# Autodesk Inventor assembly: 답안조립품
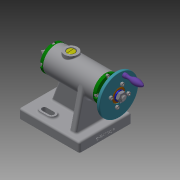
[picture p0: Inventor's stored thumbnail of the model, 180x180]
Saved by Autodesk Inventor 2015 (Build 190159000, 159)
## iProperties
Created: 2022-06
Part Number: 답안조립품
Document SubType Name: Assembly
Designer: 1048888
Author: 1048888
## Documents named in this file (18)
- C:\Users\1048888\Desktop\720606V1012\답안조립품.iam
- C:\Users\1048888\Desktop\720606V1012\나사.ipt
- C:\Users\1048888\Desktop\720606V1012\나사축.ipt
- C:\Users\1048888\Desktop\720606V1012\너트 M8.ipt
- C:\Users\1048888\Desktop\720606V1012\돌림판.ipt
- C:\Users\1048888\Desktop\720606V1012\멈춤나사 M3.ipt
- C:\Users\1048888\Desktop\720606V1012\본체.ipt
- C:\Users\1048888\Desktop\720606V1012\볼트 M3.ipt
- C:\Users\1048888\Desktop\720606V1012\부시.ipt
- C:\Users\1048888\Desktop\720606V1012\센터.ipt
- C:\Users\1048888\Desktop\720606V1012\센터홀더.ipt
- C:\Users\1048888\Desktop\720606V1012\슬리브.ipt
- C:\Users\1048888\Desktop\720606V1012\와셔.ipt
- C:\Users\1048888\Desktop\720606V1012\중공축.ipt
- C:\Users\1048888\Desktop\720606V1012\커버.ipt
- C:\Users\1048888\Desktop\720606V1012\키 4 x 4 x 10.ipt
- C:\Users\1048888\Desktop\720606V1012\플랜지.ipt
- C:\Users\1048888\Desktop\720606V1012\핸들.ipt
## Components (2 placed, 2 different names)
1. 플랜지:1 — 각도:1
2. 핸들:1
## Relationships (1: Angle 1)
- 각도:1 [Angle]: 플랜지:1
